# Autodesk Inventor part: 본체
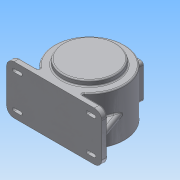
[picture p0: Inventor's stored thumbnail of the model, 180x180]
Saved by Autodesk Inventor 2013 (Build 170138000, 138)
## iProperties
Created: 2015-06
Part Number: 본체
Material: 알루미늄 6061
Document SubType Name: Modeling
Designer: Administrator
Density: 2.71 g/cm^3
Mass: 3275.77 g
Surface Area: 2302.06 cm^2
Volume: 1208.77 cm^3
Author: Administrator
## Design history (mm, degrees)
sketch "스케치1"
  geometry: C1 r 85 at (0, 0); 1 further point
  constraints: 1 centre point, 1 coincident
  dimensions: "d0" = 170 diameter of C1
extrude "돌출1" new body sketch "스케치1" stored distance "d1" = 118; taper "d2" = 0 deg
sketch "스케치2"
  geometry: C1 r 85 at (0, 0) reference; C2 r 65 at (0, 0)
  constraints: 1 centre point, 1 coincident
  dimensions: "d3" = 130 diameter of C2
extrude "돌출2" join sketch "스케치2" distance "d4" = 3; taper "d5" = 0 deg
sketch "스케치3"
  geometry: C1 r 85 at (0, 0) reference; C2 r 65 at (0, 0)
  constraints: 1 centre point, 1 coincident
  dimensions: "d6" = 130 diameter of C2
extrude "돌출3" join sketch "스케치3" distance "d7" = 13; taper "d8" = 0 deg
sketch "스케치4"
  geometry: C1 r 65 at (0, 0) reference; C2 r 47.5 at (0, 0)
  constraints: 1 centre point, 1 coincident
  dimensions: "d9" = 95 diameter of C2
extrude "돌출4" cut sketch "스케치4" distance "d10" = 11; taper "d11" = 0 deg
sketch "스케치5"
  geometry: C1 r 47.5 at (0, 0) reference; C2 r 77 at (0, 0)
  constraints: 1 centre point, 1 coincident
  dimensions: "d12" = 154 diameter of C2
extrude "돌출5" cut sketch "스케치5" distance "d13" = 102; taper "d14" = 0 deg
sketch "스케치6"
  geometry: C1 r 77 at (0, 0) reference; C2 r 31 at (0, 0)
  constraints: 1 centre point, 1 coincident
  dimensions: "d15" = 62 diameter of C2
extrude "돌출6" join sketch "스케치6" distance "d16" = 3.5; taper "d17" = -25 deg
sketch "스케치7"
  geometry: C1 r 29.368 at (0, 0) reference; C2 r 23.5 at (0, 0)
  constraints: 1 centre point, 1 coincident
  dimensions: "d18" = 47 diameter of C2
extrude "돌출7" cut sketch "스케치7" distance "d19" = 14; taper "d20" = 0 deg
sketch "스케치8"
  geometry: C1 r 23.5 at (0, 0) reference; C2 r 15 at (0, 0)
  constraints: 1 centre point, 1 coincident
  dimensions: "d21" = 30 diameter of C2
extrude "돌출8" cut sketch "스케치8" distance "d22" = 3; taper "d23" = 0 deg
fillet "모깎기1" dims "d24" = 3
fillet "모깎기2" dims "d25" = 0.3
chamfer "모따기1" distance "d26" = 1; stored, may be unused: second distance "d27" = 2, angle "d28" = 45 deg
node "작업 평면1"
sketch "스케치9"
  geometry: L1 (-115, -71)-(115, -71); L2 (115, -71)-(115, -85); L3 (115, -85)-(-115, -85); L4 (-115, -85)-(-115, -71); C1 r 77 at (0, 0) reference; C2 r 85 at (0, 0) reference; 2 further points
  constraints: 8 end point, 2 parallel, 1 horizontal, 1 midpoint, 1 perpendicular, 1 vertical alignment
  dimensions: "d30" = 14 distance of L3.end L1.start; "d32" = 85 distance from line of point (0, 0) L3; "d33" = 230 distance of L2.end L3.end
extrude "돌출9" join sketch "스케치9" stored distance "d34" = 118; taper "d35" = 0 deg
fillet "모깎기3" dims "d36" = 18
fillet "모깎기4" dims "d37" = 3
sketch "스케치10"
  geometry: L1 (55.857, -71)-(112, -71) reference; L2 (115, -74)-(115, -85) reference; L3 (115, -85)-(-115, -85) reference; L4 (-115, -85)-(-115, -74) reference; L5 (-112, -71)-(-55.857, -71) reference; L6 (-29.799, -71)-(29.799, -71) reference; L7 (-109, -71)-(-84.87, -4.703); A1 r 3 centre (-55.857, -68) between (-55.857, -71) and (-53.953, -65.682) reference; A2 r 85 centre (0, 0) between (53.953, -65.682) and (-53.953, -65.682) reference; A3 r 3 centre (55.857, -68) between (53.953, -65.682) and (55.857, -71) reference; A4 r 3 centre (112, -74) between (115, -74) and (112, -71) reference; A5 r 3 centre (-112, -74) between (-112, -71) and (-115, -74) reference; A6 r 77 centre (0, 0) between (29.799, -71) and (-29.799, -71) reference; 1 further point
  constraints: 2 end point, 1 point on circle, 1 point on line
  dimensions: "d38" = 6 distance from line of L7.start L4; "d39" = 110 deg angle of L5 L7
feature "리브1" sketch "스케치10" dims "d40" = 1, "d41" = 15, "d42" = 0, "d43" = 0, "d44" = 1, "d45" = 1
fillet "모깎기5" dims "d46" = 7.5
fillet "모깎기6" dims "d47" = 3
fillet "모깎기7" dims "d48" = 3
node "작업 평면2"
sketch "스케치11"
  geometry: L1 (-139.5, 16.5)-(-54.5, 16.5); L2 (-54.5, 16.5)-(-54.5, 101.5); L3 (-54.5, 101.5)-(-139.5, 101.5); L4 (-139.5, 101.5)-(-139.5, 16.5); L5 (-139.5, 16.5)-(-54.5, 101.5); L6 (-54.5, 16.5)-(-139.5, 101.5); 1 further point
  constraints: 12 end point, 2 midpoint, 2 parallel, 1 horizontal, 1 perpendicular
  dimensions: "d50" = 85 distance of L3.end L2.end; "d51" = 85 distance of L2.end L1.end
extrude "돌출10" join sketch "스케치11" stored distance "d52" = 118; taper "d53" = 0 deg
sketch "스케치12"
  geometry: C1 r 35 at (97, -59); 1 further point
  constraints: 1 centre point, 1 coincident
  dimensions: "d54" = 70 diameter of C1
extrude "돌출11" cut sketch "스케치12" stored distance "d55" = 118; taper "d56" = 0 deg
fillet "모깎기8" dims "d57" = 3
fillet "모깎기11" dims "d60" = 7
fillet "모깎기12" dims "d61" = 3
sketch "스케치13"
  geometry: L1 (61.5, -94.5)-(132.5, -94.5); L2 (132.5, -94.5)-(132.5, -23.5); L3 (132.5, -23.5)-(61.5, -23.5); L4 (61.5, -23.5)-(61.5, -94.5); L5 (61.5, -94.5)-(132.5, -23.5); L6 (132.5, -94.5)-(61.5, -23.5); C1 r 35 at (97, -59) reference; A1 r 7 centre (132.5, -23.5) between (139.5, -23.5) and (132.5, -16.5) reference; 4 further points
  constraints: 12 end point, 4 coincident, 2 midpoint, 2 parallel, 1 horizontal, 1 perpendicular
  dimensions: "d62" = 71 distance of L3.end L2.end (derived); "d63" = 71 distance of L2.end L1.end (derived)
hole "구멍1" sketch "스케치13" at (61.5, -23.5), (132.5, -23.5), (132.5, -94.5), (61.5, -94.5) diameter "d64" = 3.242; stored, may be unused: countersink angle "d68" = 90 deg, drill point angle "d70" = 118 deg; dims "d65" = 10, "d66" = 4, "d67" = 2, "d69" = 13
sketch "스케치14"
  geometry: C1 r 47.5 at (0, 0) reference; C2 r 77 at (0, 0)
  constraints: 1 centre point, 1 coincident
  dimensions: "d71" = 154 diameter of C2
extrude "돌출12" cut sketch "스케치14" distance "d72" = 102; taper "d73" = 0 deg
fillet "모깎기13" dims "d74" = 3
node "작업 평면3"
sketch "스케치15"
  geometry: L1 (-16, 109)-(0, 109); L2 (-16, 91)-(0, 91); L3 (0, 118)-(-194, 118) reference; L4 (-194, 109)-(-178, 109); L5 (-194, 91)-(-178, 91); A1 r 9 centre (-16, 100) between (-16, 109) and (-16, 91); A2 r 9 centre (0, 100) between (0, 91) and (0, 109); A3 r 9 centre (-178, 100) between (-178, 91) and (-178, 109); A4 r 9 centre (-194, 100) between (-194, 109) and (-194, 91); 1 further point
  constraints: 8 end point, 8 point on circle, 8 tangent, 4 centre point, 3 horizontal alignment
  dimensions: "d76" = 18 diameter of A1; "d77" = 18 diameter of A2; "d80" = 18 distance from line of A2.centre L3; "d83" = 16 distance of A2.centre A1.centre; "d84" = 18 diameter of A3; "d85" = 18 diameter of A4; "d86" = 16 distance of A4.centre A3.centre; "d87" = 194 distance of A2.centre A4.centre; "d88" = 97 horizontal distance of A2.centre point (-97, 59)
extrude "돌출13" join sketch "스케치15" distance "d89" = 3; taper "d90" = 0 deg
sketch "스케치16"
  geometry: L1 (16, -91)-(0, -91) reference; L2 (0, -109)-(16, -109) reference; L3 (0, -96)-(16, -96); L4 (16, -104)-(0, -104); A1 r 9 centre (16, -100) between (16, -109) and (16, -91) reference; A2 r 9 centre (0, -100) between (0, -91) and (0, -109) reference; A3 r 4 centre (16, -100) between (16, -104) and (16, -96); A4 r 4 centre (0, -100) between (0, -96) and (0, -104); 1 further point
  constraints: 4 end point, 4 point on circle, 2 centre point, 3 other
  dimensions: "d91" = 8 distance between parallel lines of L4 L3
extrude "돌출14" cut sketch "스케치16" stored distance "d93" = 3; taper "d94" = 0 deg
fillet "모깎기14" dims "d95" = 3
sketch "스케치17"
  geometry: C1 r 65 at (0, 0) reference; 1 further point
  constraints: 1 vertical alignment
  dimensions: "d96" = 55 distance of C1.centre point (0, 55)
hole "구멍2" sketch "스케치17" at (0, 55) diameter "d97" = 3.242; stored, may be unused: countersink angle "d101" = 90 deg, drill point angle "d103" = 118 deg; dims "d98" = 10, "d99" = 4, "d100" = 2, "d102" = 13
sketch "스케치22"
  geometry: L1 (115, -85)-(-115, -85) reference; L2 (-115, -85)-(-115, -74) reference; L3 (-112, -71)-(-111.101, -71) reference; L4 (-108.282, -69.026)-(-85.078, -5.276) reference; L5 (-42.5, 75.324)-(-42.5, 88) reference; L6 (-42.5, 88)-(-35, 88) reference; L7 (-35, 88)-(-35, 70.399) reference; L8 (35, 70.399)-(35, 88) reference; L9 (35, 88)-(42.5, 88) reference; L10 (42.5, 88)-(42.5, 75.324) reference; L11 (85.078, -5.276)-(108.282, -69.026) reference; L12 (111.101, -71)-(112, -71) reference; L13 (115, -74)-(115, -85) reference; L14 (0, 0)-(-77.036, 35.923); L15 (-1.736, 0.809)-(76.996, 0.809); A1 r 3 centre (-112, -74) between (-112, -71) and (-115, -74) reference; A2 r 85 centre (0, 0) between (-43.949, 72.756) and (-84.901, -4.105) reference; A3 r 3 centre (-45.5, 75.324) between (-43.949, 72.756) and (-42.5, 75.324) reference; A4 r 77 centre (0, 0) between (-36.575, 67.759) and (36.575, 67.759) reference; A5 r 3 centre (45.5, 75.324) between (42.5, 75.324) and (43.949, 72.756) reference; A6 r 85 centre (0, 0) between (84.901, -4.105) and (43.949, 72.756) reference; A7 r 3 centre (112, -74) between (115, -74) and (112, -71) reference; 1 further point
  constraints: 4 end point, 2 point on circle, 1 perpendicular, 1 point on line, 6 other
  dimensions: "d122" = 155 deg angle of L15 L14
  node "절단 모서리 투영3"
node "작업 평면6"
sketch "스케치23"
  geometry: 2 further points
  constraints: 1 coincident, 1 other
feature "엠보싱2" sketch "스케치23" dims "d123" = 0.5, "d124" = 0
fillet "모깎기15" dims "d110" = 3
sketch "스케치20"
  geometry: C1 r 23.5 at (0, 0) reference; C2 r 31 at (0, 0)
  constraints: 1 centre point, 1 coincident
  dimensions: "d111" = 62 diameter of C2
extrude "돌출15" join sketch "스케치20" distance "d112" = 3.5; taper "d113" = -25 deg
sketch "스케치21"
  geometry: C1 r 29.368 at (0, 0) reference; C2 r 23.5 at (0, 0)
  constraints: 1 centre point, 1 coincident
  dimensions: "d114" = 47 diameter of C2
extrude "돌출16" cut sketch "스케치21" distance "d115" = 14; taper "d116" = 0 deg
fillet "모깎기16" dims "d117" = 0.3
fillet "모깎기17" dims "d118" = 3
chamfer "모따기2" distance "d119" = 1; stored, may be unused: second distance "d120" = 2, angle "d121" = 45 deg
node "솔리드1"
mirror "대칭1"
mirror "대칭2"
mirror "대칭3"
pattern_circular "원형 패턴1" dims angle "d105" = 360 deg
node "절단 모서리 투영1"
node "절단 모서리 투영2"
other parameters: "d29" = -85, "d49" = -173, "d75" = -14
